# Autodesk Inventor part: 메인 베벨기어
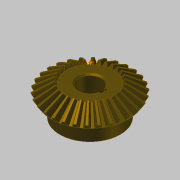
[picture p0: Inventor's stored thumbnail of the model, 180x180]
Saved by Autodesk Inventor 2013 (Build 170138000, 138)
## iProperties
Created: 2014-10
Part Number: 메인 베벨기어
Material: 강철, 탄소
Document SubType Name: Modeling
Designer: KYOUNG IL JANG
Categories: <?xml version="1.0" encoding="UTF-16"?> <MemberInstance><Categories><FamilyTemplate><FamilyTemplateParameter ValueType="xs:double" Id="1" ObjectReferenceKey="da
Mass: 269.583 g
Surface Area: 108.837 cm^2
Volume: 34.2981 cm^3
Density: 7.86 g/cm^3
CustomPartVersion: 1
Revision Number: 1
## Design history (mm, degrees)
node "맨 위 점"
node "메쉬 평면2"
sketch "톱니 본체 스케치"
  geometry: L1 (0, 0)-(28.669, -21.997); L2 (28.669, -21.997)-(31.109, -18.336); L3 (31.109, -18.336)-(0, 0); L4 (30, -20)-(0, 0); L5 (17.219, -13.212)-(18.685, -11.013); L6 (28.669, -21.997)-(17.219, -13.212); L7 (31.109, -18.336)-(18.685, -11.013); L8 (0, -39.387)-(0, 6.564) reference; L9 (0, -20)-(31.109, -20)
  constraints: 16 end point, 4 point on line, 3 perpendicular, 2 collinear, 1 horizontal alignment, 1 vertical alignment
  dimensions: "d0" = 60 diameter of L4.start L8 (= da_de); "d1" = 57.33744 diameter of L1.end L8 (= da_dfe); "d2" = 62.2188 diameter of L2.end L8 (= da_dae); "d3" = 14.4 distance between parallel lines of L2 L5 (= da_b); "d4" = 18.3359 vertical distance of L2.end L1.start (= da_ve)
revolve "톱니 본체" sketch "톱니 본체 스케치" stored, may be unused: angle "d5" = 90 deg
node "시작점"
node "톱니 평면"
sketch "시작 스케치"
  geometry: L1 (0, -23.505)-(0, 10.645) reference; L2 (-0.709, -2.928)-(0.709, -2.928); A1 r 19.188 centre (-19.457, -7.014) between (-0.709, -2.928) and (-3.232, 3.229); A2 r 19.188 centre (19.457, -7.014) between (3.232, 3.229) and (0.709, -2.928); A3 r 57.403 centre (0, -54.083) between (3.232, 3.229) and (-3.232, 3.229); 1 further point
  constraints: 6 point on circle, 3 centre point, 3 symmetric about line, 2 end point, 1 coincident, 1 perpendicular, 1 other
  dimensions: "d7" = 19.18795 radius of A1 (= fd_rr); "d8" = 19.45712 horizontal distance of point (0, -54.083) A1.centre (= fd_x); "d9" = 47.06905 vertical distance of point (0, -54.083) A1.centre (= fd_y); "d57" = 57.40327 radius of A3 (= 0.5 x fd_dva + 0.3 x da_he); "d58" = 51.15527 distance from line of A3.centre L2 (= 0.5 x fd_dva - 1.12 x da_he)
node "끝점"
  node "끝 평면"
sketch "3D 스케치 오른쪽"
  node "Helical Curve Right" dims "d65" = 229.90621 (computed from da_dm, da_delta, da_beta), "d66" = 31.5, "d67" = 60 (= da_de), "d68" = -9.82794 (= -da_delta), "d69" = 8.10972 (computed from fd_loft, da_delta)
node "끝 평면 오른쪽"
sketch "끝 스케치 오른쪽"
  geometry: L1 (0, -41.54)-(0, 13.178) reference; L2 (-0.422, -1.69)-(0.422, -1.69); A1 r 11.427 centre (-11.587, -4.123) between (-0.422, -1.69) and (-1.925, 1.977); A2 r 11.427 centre (11.587, -4.123) between (1.925, 1.977) and (0.422, -1.69); A3 r 34.184 centre (0, -32.153) between (1.925, 1.977) and (-1.925, 1.977); 1 further point
  constraints: 6 point on circle, 3 centre point, 3 symmetric about line, 2 end point, 1 coincident, 1 perpendicular, 1 other
  dimensions: "d70" = 11.58699 horizontal distance of A3.centre A1.centre (computed from fd_x, fd_ratio); "d71" = 28.03028 vertical distance of point (0, -32.153) A1.centre (computed from fd_y, fd_ratio); "d72" = 11.4267 radius of A1 (computed from fd_rr, fd_ratio); "d73" = 30.46369 distance from line of point (0, -32.153) L2 (computed from d58, fd_ratio); "d74" = 34.18446 radius of A3 (computed from d57, fd_ratio)
feature "로프트 오른쪽" sketch "끝 스케치 오른쪽" dims "d75" = 0, "d77" = 0, "d79" = 0, "d80" = 90 deg, "d85" = 20, "d92" = 90 deg, "d93" = 90 deg, "da_teethtype" = 0 [user parameter]
sketch "3D 스케치 왼쪽"
  node "Helical Curve Left" dims "d26" = 229.90621 (computed from da_dm, da_delta, da_beta), "d27" = 8.10972 (computed from fd_loft, da_delta), "d28" = 60 (= da_de), "d29" = -9.82794 (= -da_delta)
node "끝 평면 왼쪽"
sketch "끝 스케치 왼쪽" dims "d56" = 10.3728 (derived)
  geometry: L1 (0, -43.753)-(0, 15.405) reference; L2 (-0.422, -1.678)-(0.422, -1.678); A1 r 11.427 centre (-11.587, -4.111) between (-0.422, -1.678) and (-1.925, 1.988); A2 r 11.427 centre (11.587, -4.111) between (1.925, 1.988) and (0.422, -1.678); A3 r 34.184 centre (0, -32.142) between (1.925, 1.988) and (-1.925, 1.988); 2 further points; 1 other entity
  constraints: 6 point on circle, 3 centre point, 3 symmetric about line, 2 end point, 1 coincident, 2 other
  dimensions: "d30" = 11.4267 radius of A1 (computed from fd_rr, fd_ratio); "d31" = 11.58699 horizontal distance of point (0, -32.142) A1.centre (computed from fd_x, fd_ratio); "d32" = 28.03028 vertical distance of A1.centre point (0, -32.142) (computed from fd_y, fd_ratio); "d61" = 34.18446 radius of A3 (computed from d57, fd_ratio); "d62" = 30.46369 distance from line of point (0, -32.142) L2 (computed from d58, fd_ratio)
feature "로프트 왼쪽" sketch "끝 스케치 왼쪽" dims "d35" = 0, "d37" = 0, "d39" = 0, "d40" = 90 deg, "d84" = 10, "d90" = 90 deg, "d91" = 90 deg, "da_teethtype" = 0 [user parameter]
sketch "본체 스케치"
  geometry: L1 (0, -35.038)-(0, -19.531) reference; L2 (28.669, -21.997)-(17.219, -13.212) reference; L3 (17.219, -13.212)-(0, -13.212); L4 (28.669, -21.997)-(0, -21.997)
  constraints: 4 end point, 2 perpendicular, 2 point on line
revolve "본체 고정" sketch "본체 스케치" stored, may be unused: angle "d46" = 90 deg
feature "피치 지름" dims angle "d47" = 90 deg
sketch "스케치8"
  geometry: C1 r 22.5 at (0, 0); 1 further point
  constraints: 1 centre point, 1 coincident
  dimensions: "d94" = 45 diameter of C1
extrude "돌출1" join sketch "스케치8" distance "d95" = 13; taper "d96" = 0 deg
sketch "스케치9"
  geometry: 1 further point
hole "구멍1" sketch "스케치9" at (0, 0) diameter "d97" = 17; stored, may be unused: countersink angle "d101" = 90 deg, drill point angle "d103" = 118 deg; dims "d98" = 6, "d99" = 4, "d100" = 2, "d102" = 8
sketch "스케치10"
  geometry: L1 (8.124, 2.5)-(10.8, 2.5); L2 (10.8, 2.5)-(10.8, -2.5); L3 (10.8, -2.5)-(8.124, -2.5); A1 r 8.5 centre (0, 0) between (8.124, 2.5) and (8.124, -2.5) reference; 1 further point
  constraints: 6 end point, 2 parallel, 2 point on circle, 1 horizontal, 1 perpendicular
  dimensions: "d104" = 5 distance of L1.end L2.end; "d112" = 19.3 dimension on A1 L2
extrude "돌출2" cut sketch "스케치10" stored distance "d106" = 10; taper "d107" = 0 deg
chamfer "모따기1" distance "d108" = 1; stored, may be unused: second distance "d109" = 2, angle "d110" = 45 deg
fillet "모깎기1" dims "d111" = 2
body "Solid1"
feature "로프트" dims "d17" = 0, "d18" = 90 deg, "d19" = 0, "d20" = 90 deg, "d89" = 0, "da_teethtype" = 0 [user parameter]
pattern_circular "원형 패턴" dims angle "d22" = 360 deg, "d88" = 0, "da_teethtype" = 0 [user parameter]
pattern_circular "원형 패턴 오른쪽" dims angle "d82" = 360 deg, "da_teethtype" = 0 [user parameter]
pattern_circular "원형 패턴 왼쪽" dims angle "d42" = 360 deg, "da_teethtype" = 0 [user parameter]
sketch "끝 스케치"
  geometry: L1 (0, -15.359)-(0, 6.983) reference; L2 (-0.422, -1.69)-(0.422, -1.69); A1 r 11.427 centre (-11.587, -4.123) between (-0.422, -1.69) and (-1.925, 1.977); A2 r 11.427 centre (11.587, -4.123) between (1.925, 1.977) and (0.422, -1.69); A3 r 34.184 centre (0, -32.153) between (1.925, 1.977) and (-1.925, 1.977); 1 further point
  constraints: 6 point on circle, 3 centre point, 3 symmetric about line, 2 end point, 1 coincident, 1 other
  dimensions: "d12" = 11.4267 radius of A1 (computed from fd_rr, fd_ratio); "d15" = 11.58699 horizontal distance of A1.centre point (0, -32.153) (computed from fd_x, fd_ratio); "d16" = 28.03028 vertical distance of A1.centre point (0, -32.153) (computed from fd_y, fd_ratio); "d59" = 34.18446 radius of A3 (computed from d57, fd_ratio); "d60" = 30.46369 distance from line of A3.centre L2 (computed from d58, fd_ratio)
sketch "Sketch6"
  geometry: L1 (30, -20)-(0, 0) reference; L2 (0, -37.8)-(0, 6.3) reference
body "Srf1"
other parameters: "da_b" = 14.4 [user parameter; used in 2 equation terms], "da_de" = 60 [user parameter; used in 4 equation terms], "da_dae" = 62.2188 [user parameter; used in 2 equation terms], "da_dfe" = 57.33744 [user parameter; used in 1 equation term], "da_le" = 36.05551 [user parameter; used in 1 equation term], "da_omega" = 90 deg [user parameter; used in 1 equation term], "da_beta" = 0 [user parameter; used in 2 equation terms], "da_delta" = 9.82794 [user parameter; used in 8 equation terms], "da_alpha" = 20 deg [user parameter; used in 2 equation terms], "da_he" = 4.4 [user parameter; used in 4 equation terms], "da_ve" = 18.3359 [user parameter; used in 1 equation term], "fd_dv" = 108.16654 (computed from da_de, da_delta) [user parameter; used in 1 equation term], "fd_dva" = 112.16654 (computed from da_dae, da_delta) [user parameter; used in 3 equation terms], "fd_dvb" = 101.6433 (computed from fd_dv, da_alpha) [user parameter; used in 2 equation terms], "da_zv" = 540.83269 [user parameter; used in 1 equation term], "fd_loft" = 14.62 (= da_b + 0.05 x da_he) [user parameter; used in 4 equation terms], "fd_ratio" = 5.95514 (computed from da_le, fd_loft) [user parameter; used in 15 equation terms], "fd_rr" = 19.18795 (computed from fd_dd, fd_dvb) [user parameter; used in 6 equation terms], "fd_angle" = 0.29367 (computed from da_zv) [user parameter; used in 4 equation terms], "fd_x1" = 1.58802 (computed from da_dvw, fd_angle) [user parameter; used in 1 equation term], "fd_y1" = 54.05995 (computed from da_dvw, fd_angle) [user parameter; used in 1 equation term], "fd_x2" = 17.8691 (computed from fd_rr, fd_angle2, fd_angle) [user parameter; used in 1 equation term], "fd_y2" = 6.9909 (computed from fd_rr, fd_angle2, fd_angle) [user parameter; used in 1 equation term], "fd_x" = 19.45712 (= fd_x1 + fd_x2) [user parameter; used in 4 equation terms], "fd_y" = 47.06905 (= fd_y1 - fd_y2) [user parameter; used in 4 equation terms], "fd_angle2" = 3.43555 (computed from fd_dvb, fd_dd, da_alpha) [user parameter; used in 2 equation terms], "fd_dd" = 108.64654 (= fd_dva - 0.8 x da_he) [user parameter; used in 2 equation terms], "da_dvw" = 108.16654 [user parameter; used in 2 equation terms], "d11" = 14.62 (= fd_loft), "da_dm" = 48.01848 [user parameter; used in 2 equation terms], "da_x" = 0 [user parameter], "da_m" = 2 [user parameter], "d48" = 0, "d49" = 0, "d50" = 90 deg (= da_omega), "d51" = 6 deg (computed from da_z), "d52" = 0, "d53" = 0, "d54" = 0
